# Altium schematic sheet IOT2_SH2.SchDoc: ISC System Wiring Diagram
size B; DrawnBy: Filiberto Clara; Engineer: Filiberto Clara; Organization: LIGO Laboratory; Address1: California Institute of Technology; Address2: Massachusetts Institute of Technology; SheetNumber: 27; SheetTotal: 39
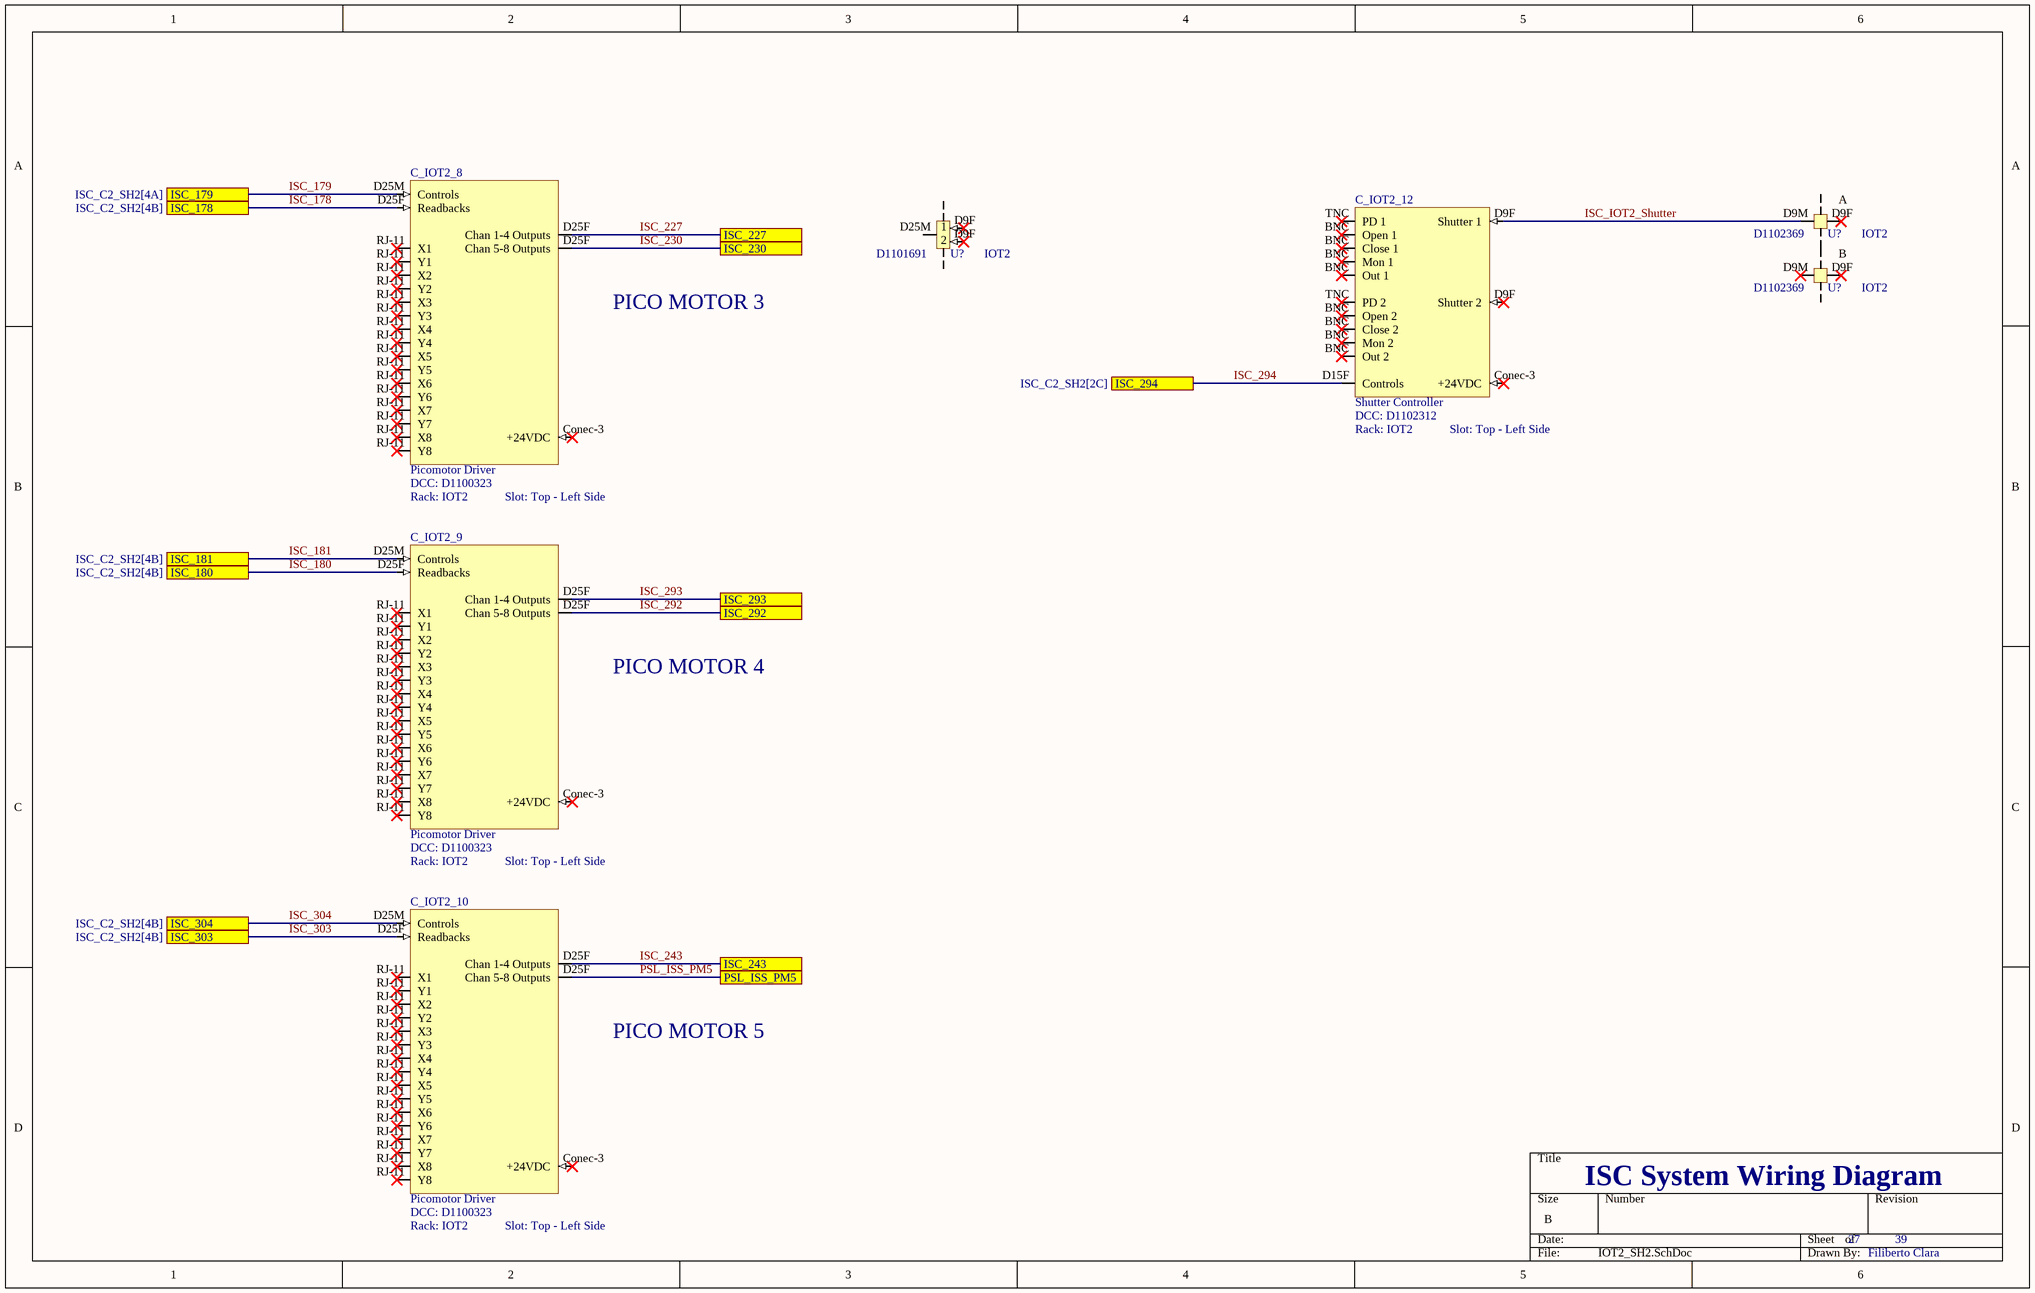
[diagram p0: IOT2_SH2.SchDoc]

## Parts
C_IOT2_8  Picomotor Driver  DCC: D1100323  Rack: IOT2  Slot: Top - Left Side
C_IOT2_9  Picomotor Driver  DCC: D1100323  Rack: IOT2  Slot: Top - Left Side
C_IOT2_10  Picomotor Driver  DCC: D1100323  Rack: IOT2  Slot: Top - Left Side
C_IOT2_11  DCC: D1101691  Rack: IOT2  Slot: U?  (hidden comment: Patch Panel Picomotor Breakout)
C_IOT2_12  Shutter Controller  DCC: D1102312  Rack: IOT2  Slot: Top - Left Side
C_IOT2_13  DCC: D1102369  Rack: IOT2  Slot: U?  (hidden comment: Patch Panel Uniblitz Shutters)  (parts A,B of 2)

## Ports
ISC_178 (see ISC_C2_SH2[4B]), ISC_179 (see ISC_C2_SH2[4A]), ISC_180 (see ISC_C2_SH2[4B]), ISC_181 (see ISC_C2_SH2[4B]), ISC_227, ISC_230, ISC_243, ISC_292, ISC_293, ISC_294 (see ISC_C2_SH2[2C]), ISC_303 (see ISC_C2_SH2[4B]), ISC_304 (see ISC_C2_SH2[4B]), PSL_ISS_PM5

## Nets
ISC_178: C_IOT2_8.D25F(Readbacks) ; port ISC_178
ISC_179: C_IOT2_8.D25M(Controls) ; port ISC_179
ISC_180: C_IOT2_9.D25F(Readbacks) ; port ISC_180
ISC_181: C_IOT2_9.D25M(Controls) ; port ISC_181
ISC_227: C_IOT2_8.D25F(Chan_1-4_Outputs) ; port ISC_227
ISC_230: C_IOT2_8.D25F(Chan_5-8_Outputs) ; port ISC_230
ISC_243: C_IOT2_10.D25F(Chan_1-4_Outputs) ; port ISC_243
ISC_292: C_IOT2_9.D25F(Chan_5-8_Outputs) ; port ISC_292
ISC_293: C_IOT2_9.D25F(Chan_1-4_Outputs) ; port ISC_293
ISC_294: C_IOT2_12.D15F(Controls) ; port ISC_294
ISC_303: C_IOT2_10.D25F(Readbacks) ; port ISC_303
ISC_304: C_IOT2_10.D25M(Controls) ; port ISC_304
ISC_IOT2_Shutter: C_IOT2_12.D9F(Shutter_1) C_IOT2_13.D9M(Output)
PSL_ISS_PM5: C_IOT2_10.D25F(Chan_5-8_Outputs) ; port PSL_ISS_PM5

Not connected (* = marked no-connect by the designer): C_IOT2_8 Conec-3(+24VDC)* RJ-11(X1)*; C_IOT2_9 Conec-3(+24VDC)* RJ-11(X1)*; C_IOT2_10 Conec-3(+24VDC)* RJ-11(X1)*; C_IOT2_11 D9F(2)* D25M(Pico); C_IOT2_12 BNC(Open_1)* Conec-3(+24VDC)* TNC(PD_1)*; C_IOT2_13 D9F(Output)*

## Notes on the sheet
- PICO MOTOR 3
- PICO MOTOR 4
- PICO MOTOR 5

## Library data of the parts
C_IOT2_8-C_IOT2_10 = Picomotor Driver: Serial: Sxxxxxxx; System: ISC
C_IOT2_11 = Patch Panel Picomotor Breakout: Patch Panel (D1101691); Serial: Sxxxxxxx; System: ISC
C_IOT2_12 = Shutter Controller: Serial: Sxxxxxxx; System: ISC
C_IOT2_13 = Patch Panel Uniblitz Shutters: Patch Panel (D1102369); Serial: Sxxxxxxx; System: ISC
